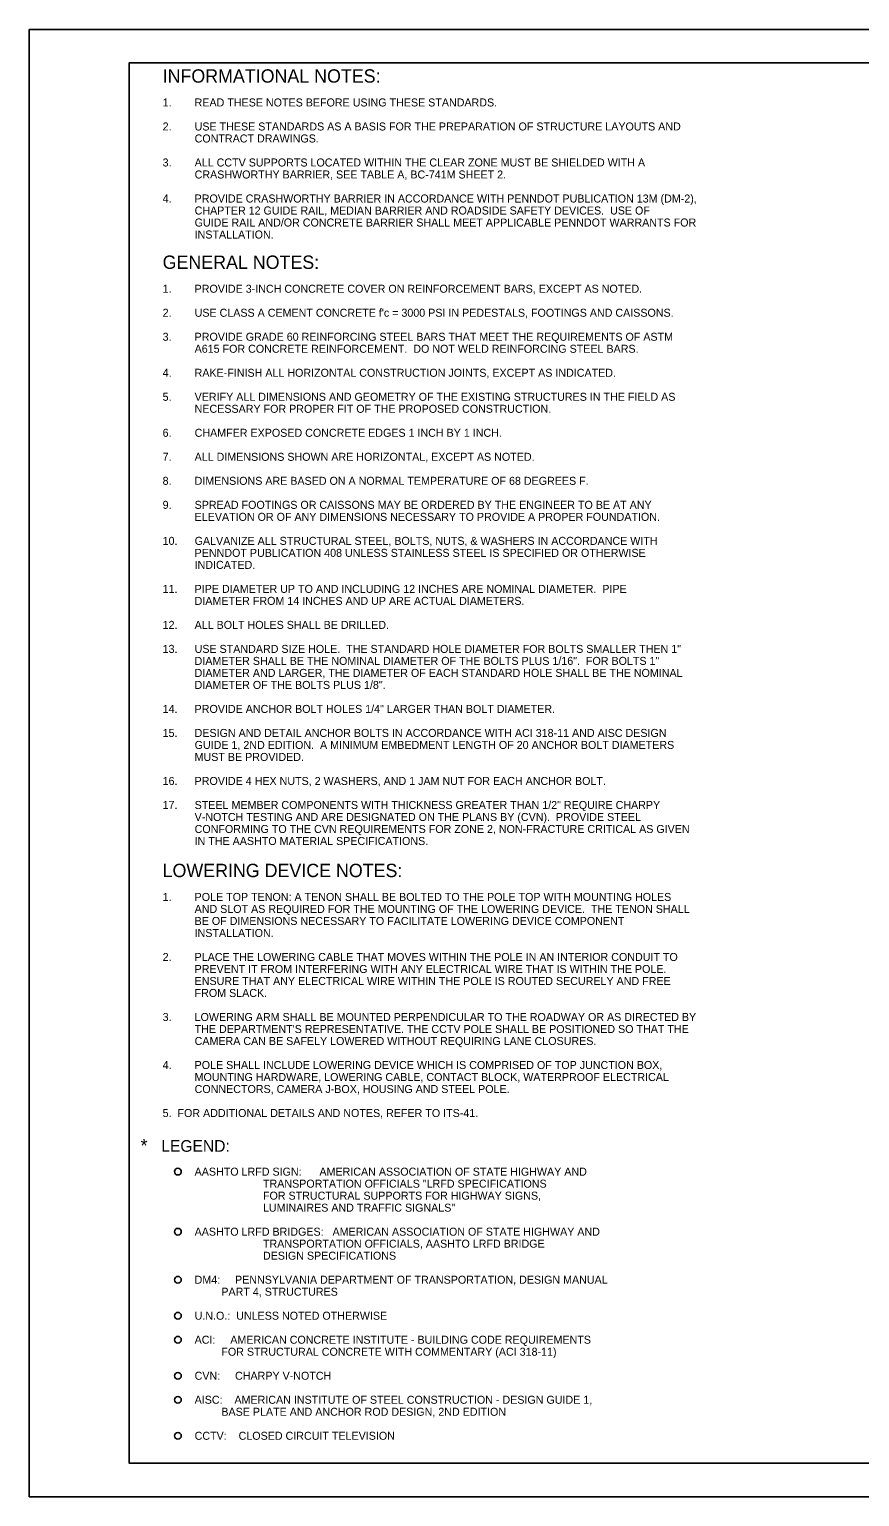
# Model space of a CAD drawing. Extents: x 1299105.1 to 1299141.9, y 239690 to 239712.
# Drawn here: x 1299105.09 to 1299117.55, y 239689.98 to 239711.98 of the extents above; entities that cross this region are included whole.
import ezdxf

# ---------------------------------------------------------------- set-up
doc = ezdxf.new("R2010")
doc.units = 0
for name, color, linetype in [('DIM TXT', 7, 'Continuous'), ('GS_plotshape_p', 7, 'Continuous'), ('Level 1', 7, 'Continuous')]:
    doc.layers.add(name, color=color, linetype=linetype)

msp = doc.modelspace()

# ---------------------------------------------------------------- linework, layer by layer
at = {"layer": 'DIM TXT'}
for centre in [(1299107.32, 239694.857), (1299107.32, 239693.957), (1299107.32, 239693.237), (1299107.32, 239692.697), (1299107.32, 239692.337), (1299107.32, 239691.797), (1299107.32, 239691.437), (1299107.32, 239690.897)]:
    msp.add_circle(centre, 0.05, dxfattribs=at)
at = {"layer": 'GS_plotshape_p'}
msp.add_lwpolyline([(1299105.09, 239711.984), (1299139.09, 239711.984), (1299139.09, 239689.984), (1299105.09, 239689.984)], close=True, dxfattribs=at)
at = {"layer": 'Level 1'}
msp.add_lwpolyline([(1299138.59, 239690.484), (1299106.59, 239690.484), (1299106.59, 239711.484), (1299138.59, 239711.484)], close=True, dxfattribs=at)

# ---------------------------------------------------------------- texts
at = {"layer": 'DIM TXT'}
for s, height, p in [('INFORMATIONAL NOTES:', 0.2, (1299107.09, 239711.185)), ('1.', 0.12, (1299107.09, 239710.828)), ('READ THESE NOTES BEFORE USING THESE STANDARDS.', 0.12, (1299107.57, 239710.828)), ('2.', 0.12, (1299107.09, 239710.468)), ('USE THESE STANDARDS AS A BASIS FOR THE PREPARATION OF STRUCTURE LAYOUTS AND ', 0.12, (1299107.57, 239710.468)), ('CONTRACT DRAWINGS.', 0.12, (1299107.57, 239710.288)), ('3.', 0.12, (1299107.09, 239709.928)), ('ALL CCTV SUPPORTS LOCATED WITHIN THE CLEAR ZONE MUST BE SHIELDED WITH A ', 0.12, (1299107.57, 239709.928)), ('CRASHWORTHY BARRIER, SEE TABLE A, BC-741M SHEET 2.', 0.12, (1299107.57, 239709.748)), ('4.', 0.12, (1299107.09, 239709.388)), ('PROVIDE CRASHWORTHY BARRIER IN ACCORDANCE WITH PENNDOT PUBLICATION 13M (DM-2), ', 0.12, (1299107.57, 239709.388)), ('CHAPTER 12 GUIDE RAIL, MEDIAN BARRIER AND ROADSIDE SAFETY DEVICES.  USE OF ', 0.12, (1299107.57, 239709.208)), ('GUIDE RAIL AND/OR CONCRETE BARRIER SHALL MEET APPLICABLE PENNDOT WARRANTS FOR ', 0.12, (1299107.57, 239709.028)), ('INSTALLATION.', 0.12, (1299107.57, 239708.848)), ('GENERAL NOTES:', 0.2, (1299107.09, 239708.393)), ('1.', 0.12, (1299107.09, 239708.035)), ('PROVIDE 3-INCH CONCRETE COVER ON REINFORCEMENT BARS, EXCEPT AS NOTED.', 0.12, (1299107.57, 239708.035)), ('2.', 0.12, (1299107.09, 239707.675)), ("USE CLASS A CEMENT CONCRETE f'c = 3000 PSI IN PEDESTALS, FOOTINGS AND CAISSONS.", 0.12, (1299107.57, 239707.675)), ('3.', 0.12, (1299107.09, 239707.315)), ('PROVIDE GRADE 60 REINFORCING STEEL BARS THAT MEET THE REQUIREMENTS OF ASTM ', 0.12, (1299107.57, 239707.315)), ('A615 FOR CONCRETE REINFORCEMENT.  DO NOT WELD REINFORCING STEEL BARS.', 0.12, (1299107.57, 239707.135)), ('4.', 0.12, (1299107.09, 239706.775)), ('RAKE-FINISH ALL HORIZONTAL CONSTRUCTION JOINTS, EXCEPT AS INDICATED.', 0.12, (1299107.57, 239706.775)), ('5.', 0.12, (1299107.09, 239706.415)), ('VERIFY ALL DIMENSIONS AND GEOMETRY OF THE EXISTING STRUCTURES IN THE FIELD AS ', 0.12, (1299107.57, 239706.415)), ('NECESSARY FOR PROPER FIT OF THE PROPOSED CONSTRUCTION.', 0.12, (1299107.57, 239706.235)), ('6.', 0.12, (1299107.09, 239705.875)), ('CHAMFER EXPOSED CONCRETE EDGES 1 INCH BY 1 INCH.', 0.12, (1299107.57, 239705.875)), ('7.', 0.12, (1299107.09, 239705.515)), ('ALL DIMENSIONS SHOWN ARE HORIZONTAL, EXCEPT AS NOTED.', 0.12, (1299107.57, 239705.515)), ('8.', 0.12, (1299107.09, 239705.155)), ('DIMENSIONS ARE BASED ON A NORMAL TEMPERATURE OF 68 DEGREES F.', 0.12, (1299107.57, 239705.155)), ('9.', 0.12, (1299107.09, 239704.795)), ('SPREAD FOOTINGS OR CAISSONS MAY BE ORDERED BY THE ENGINEER TO BE AT ANY ', 0.12, (1299107.57, 239704.795)), ('ELEVATION OR OF ANY DIMENSIONS NECESSARY TO PROVIDE A PROPER FOUNDATION.', 0.12, (1299107.57, 239704.615)), ('10.', 0.12, (1299107.09, 239704.255)), ('GALVANIZE ALL STRUCTURAL STEEL, BOLTS, NUTS, & WASHERS IN ACCORDANCE WITH ', 0.12, (1299107.57, 239704.255)), ('PENNDOT PUBLICATION 408 UNLESS STAINLESS STEEL IS SPECIFIED OR OTHERWISE ', 0.12, (1299107.57, 239704.075)), ('INDICATED.', 0.12, (1299107.57, 239703.895)), ('11.', 0.12, (1299107.09, 239703.535)), ('PIPE DIAMETER UP TO AND INCLUDING 12 INCHES ARE NOMINAL DIAMETER.  PIPE ', 0.12, (1299107.57, 239703.535)), ('DIAMETER FROM 14 INCHES AND UP ARE ACTUAL DIAMETERS.', 0.12, (1299107.57, 239703.355)), ('12.', 0.12, (1299107.09, 239702.995)), ('ALL BOLT HOLES SHALL BE DRILLED.', 0.12, (1299107.57, 239702.995)), ('13.', 0.12, (1299107.09, 239702.635)), ('USE STANDARD SIZE HOLE.  THE STANDARD HOLE DIAMETER FOR BOLTS SMALLER THEN 1" ', 0.12, (1299107.57, 239702.635)), ('DIAMETER SHALL BE THE NOMINAL DIAMETER OF THE BOLTS PLUS 1/16".  FOR BOLTS 1" ', 0.12, (1299107.57, 239702.455)), ('DIAMETER AND LARGER, THE DIAMETER OF EACH STANDARD HOLE SHALL BE THE NOMINAL ', 0.12, (1299107.57, 239702.275)), ('DIAMETER OF THE BOLTS PLUS 1/8".', 0.12, (1299107.57, 239702.095)), ('14.', 0.12, (1299107.09, 239701.735)), ('PROVIDE ANCHOR BOLT HOLES 1/4" LARGER THAN BOLT DIAMETER.', 0.12, (1299107.57, 239701.735)), ('15.', 0.12, (1299107.09, 239701.375)), ('DESIGN AND DETAIL ANCHOR BOLTS IN ACCORDANCE WITH ACI 318-11 AND AISC DESIGN ', 0.12, (1299107.57, 239701.375)), ('GUIDE 1, 2ND EDITION.  A MINIMUM EMBEDMENT LENGTH OF 20 ANCHOR BOLT DIAMETERS ', 0.12, (1299107.57, 239701.195)), ('MUST BE PROVIDED.', 0.12, (1299107.57, 239701.015)), ('16.', 0.12, (1299107.09, 239700.655)), ('PROVIDE 4 HEX NUTS, 2 WASHERS, AND 1 JAM NUT FOR EACH ANCHOR BOLT.', 0.12, (1299107.57, 239700.655)), ('17.', 0.12, (1299107.09, 239700.295)), ('STEEL MEMBER COMPONENTS WITH THICKNESS GREATER THAN 1/2" REQUIRE CHARPY ', 0.12, (1299107.57, 239700.295)), ('V-NOTCH TESTING AND ARE DESIGNATED ON THE PLANS BY (CVN).  PROVIDE STEEL ', 0.12, (1299107.57, 239700.115)), ('CONFORMING TO THE CVN REQUIREMENTS FOR ZONE 2, NON-FRACTURE CRITICAL AS GIVEN ', 0.12, (1299107.57, 239699.935)), ('IN THE AASHTO MATERIAL SPECIFICATIONS.', 0.12, (1299107.57, 239699.755)), ('LOWERING DEVICE NOTES:', 0.2, (1299107.09, 239699.273)), ('1.', 0.12, (1299107.09, 239698.916)), ('POLE TOP TENON: A TENON SHALL BE BOLTED TO THE POLE TOP WITH MOUNTING HOLES ', 0.12, (1299107.57, 239698.916)), ('AND SLOT AS REQUIRED FOR THE MOUNTING OF THE LOWERING DEVICE.  THE TENON SHALL ', 0.12, (1299107.57, 239698.736)), ('BE OF DIMENSIONS NECESSARY TO FACILITATE LOWERING DEVICE COMPONENT ', 0.12, (1299107.57, 239698.556)), ('INSTALLATION.', 0.12, (1299107.57, 239698.376)), ('2.', 0.12, (1299107.09, 239698.016)), ('PLACE THE LOWERING CABLE THAT MOVES WITHIN THE POLE IN AN INTERIOR CONDUIT TO ', 0.12, (1299107.57, 239698.016)), ('PREVENT IT FROM INTERFERING WITH ANY ELECTRICAL WIRE THAT IS WITHIN THE POLE.  ', 0.12, (1299107.57, 239697.836)), ('ENSURE THAT ANY ELECTRICAL WIRE WITHIN THE POLE IS ROUTED SECURELY AND FREE ', 0.12, (1299107.57, 239697.656)), ('FROM SLACK.', 0.12, (1299107.57, 239697.476)), ('3.', 0.12, (1299107.09, 239697.116)), ("THE DEPARTMENT'S REPRESENTATIVE. THE CCTV POLE SHALL BE POSITIONED SO THAT THE ", 0.12, (1299107.57, 239696.936)), ('LOWERING ARM SHALL BE MOUNTED PERPENDICULAR TO THE ROADWAY OR AS DIRECTED BY ', 0.12, (1299107.57, 239697.116)), ('CAMERA CAN BE SAFELY LOWERED WITHOUT REQUIRING LANE CLOSURES.', 0.12, (1299107.57, 239696.756)), ('4.', 0.12, (1299107.09, 239696.396)), ('POLE SHALL INCLUDE LOWERING DEVICE WHICH IS COMPRISED OF TOP JUNCTION BOX, ', 0.12, (1299107.57, 239696.396)), ('MOUNTING HARDWARE, LOWERING CABLE, CONTACT BLOCK, WATERPROOF ELECTRICAL ', 0.12, (1299107.57, 239696.216)), ('CONNECTORS, CAMERA J-BOX, HOUSING AND STEEL POLE.', 0.12, (1299107.57, 239696.036)), ('5.  FOR ADDITIONAL DETAILS AND NOTES, REFER TO ITS-41.', 0.12, (1299107.09, 239695.676)), ('*', 0.2, (1299106.759, 239695.148)), ('LEGEND:', 0.175, (1299107.07, 239695.155)), ('AASHTO LRFD SIGN:      AMERICAN ASSOCIATION OF STATE HIGHWAY AND', 0.12, (1299107.57, 239694.797)), ('                       TRANSPORTATION OFFICIALS "LRFD SPECIFICATIONS', 0.12, (1299107.57, 239694.617)), ('                       FOR STRUCTURAL SUPPORTS FOR HIGHWAY SIGNS,', 0.12, (1299107.57, 239694.437)), ('                       LUMINAIRES AND TRAFFIC SIGNALS"', 0.12, (1299107.57, 239694.257)), ('AASHTO LRFD BRIDGES:   AMERICAN ASSOCIATION OF STATE HIGHWAY AND', 0.12, (1299107.57, 239693.897)), ('                       TRANSPORTATION OFFICIALS, AASHTO LRFD BRIDGE', 0.12, (1299107.57, 239693.717)), ('                       DESIGN SPECIFICATIONS', 0.12, (1299107.57, 239693.537)), ('DM4:     PENNSYLVANIA DEPARTMENT OF TRANSPORTATION, DESIGN MANUAL', 0.12, (1299107.57, 239693.177)), ('         PART 4, STRUCTURES', 0.12, (1299107.57, 239692.997)), ('U.N.O.:  UNLESS NOTED OTHERWISE', 0.12, (1299107.57, 239692.637)), ('ACI:     AMERICAN CONCRETE INSTITUTE - BUILDING CODE REQUIREMENTS', 0.12, (1299107.57, 239692.277)), ('         FOR STRUCTURAL CONCRETE WITH COMMENTARY (ACI 318-11)', 0.12, (1299107.57, 239692.097)), ('CVN:     CHARPY V-NOTCH', 0.12, (1299107.57, 239691.737)), ('AISC:    AMERICAN INSTITUTE OF STEEL CONSTRUCTION - DESIGN GUIDE 1,', 0.12, (1299107.57, 239691.377)), ('         BASE PLATE AND ANCHOR ROD DESIGN, 2ND EDITION', 0.12, (1299107.57, 239691.197)), ('CCTV:    CLOSED CIRCUIT TELEVISION', 0.12, (1299107.57, 239690.837))]:
    msp.add_text(s, height=height, dxfattribs=at).set_placement(p)

doc.saveas('drawing.dxf')
